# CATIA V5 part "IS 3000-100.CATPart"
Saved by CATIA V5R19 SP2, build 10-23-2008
Part number: IS 3000-100
Bounding box of the stored display mesh (mm): x -47.487 to 47.487, y -47.487 to 47.487, z 0 to 320
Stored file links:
  C:\Users\Bora\Desktop\3D Katı model\IS serisi\IS 3000\IS 3000-100.CATPart
  C:\Program Files\Dassault Systemes\B19\intel_a\reffiles\standard\MetricThickPitch.txt
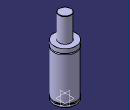
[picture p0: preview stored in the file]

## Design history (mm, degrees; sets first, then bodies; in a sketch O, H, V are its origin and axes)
Body1 (main body)
  Sketch1 on yz-plane, origin (0, 0, 0), H (0, 1, 0), V (0, 0, 1)
    point P1 (47.5, 198.5)
    point P4 (47.5, 193.5)
    point P7 (25, 319)
    point P9 (25, 319)
    point P13 (47.5, 198.5)
    point P14 (47.5, 193.5)
    line L1 (47.5, 198.5) -> (47.5, 217)
    line L2 (47.5, 13) -> (47.5, 193.5)
    line L3 (43.5, 13) -> (43.5, 8)
    arc A1 centre (24, 319) radius 1 from (25, 319) to (24, 320) ccw
    line L4 (25, 319) -> (25, 217)
    line L5 (47.5, 0) -> (47.5, 8)
    arc A2 centre (47.5, 196) radius 2.5 from (47.5, 198.5) to (47.5, 193.5) ccw
    line L6 (24, 320) -> (0, 320)
    point P15 (0, 320)
    line L7 (25, 217) -> (47.5, 217)
    line L8 (43.5, 13) -> (47.5, 13)
    line L9 (43.5, 8) -> (47.5, 8)
    line L10 (47.5, 0) -> (0, 0)
    coincidence: P15 V, P1 P13, P4 P14, P7 P9
    tangency: L6 A1
    horizontal: L7 H, L8 H, L10 H
  Shaft1: profile Sketch1, axis Sketch1.V, angle 360
  Sketch2 on face of Shaft1 from Sketch1.L10, origin (0, 0, 0), H (1, 0, 0), V (0, -1, 0)
    point P1 (30, 0)
    distance P1 V = 30
  Hole1: placed by Sketch2, at (30, 0, 0) direction (0, 0, 1), diameter 6.647, depth 13, threaded "M8", thread diameter 8, thread depth 13, pitch 1.25
  CircPattern1: of Hole1, instances 4, angular step 90, axis from xy-plane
